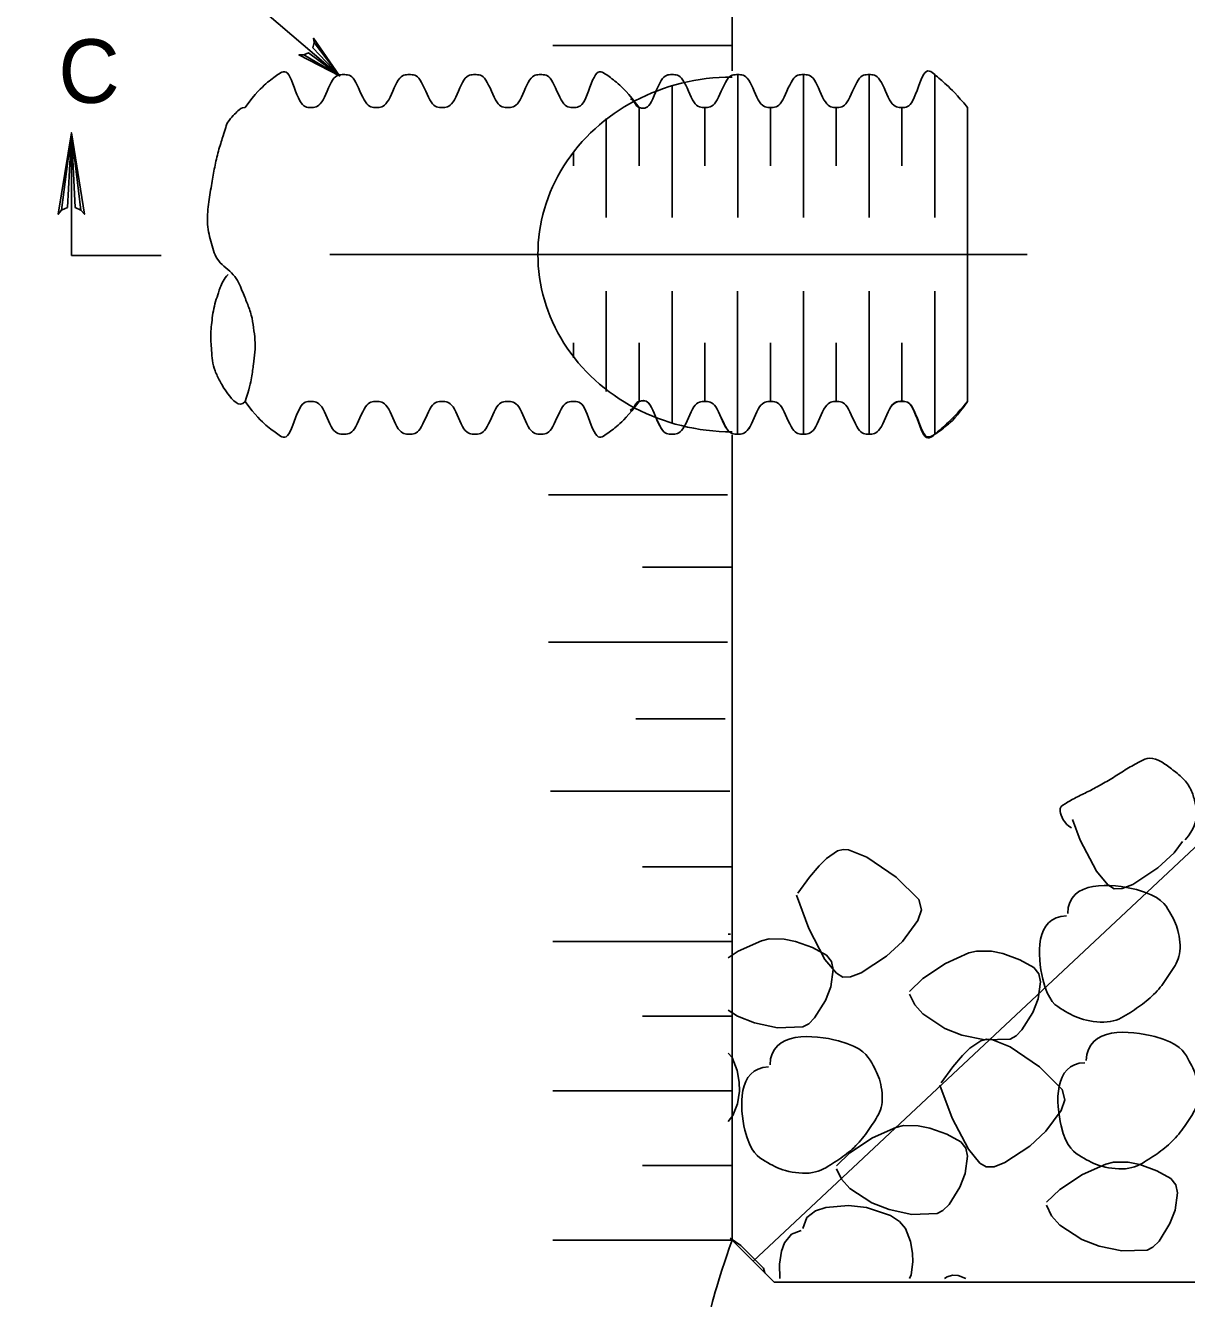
# Model space of a CAD drawing. Extents: x 636183 to 639890, y 299162 to 300538.
# Drawn here: x 638561.9 to 638653.3, y 300331.8 to 300431.9 of the extents above; entities that cross this region are included whole.
import ezdxf

# ---------------------------------------------------------------- set-up
doc = ezdxf.new("R2010")
doc.units = 0
doc.layers.add('Default', color=7, linetype='Continuous')

msp = doc.modelspace()

# ---------------------------------------------------------------- linework, layer by layer
at = {"layer": 'Default'}
for p, q in [((638617.52, 300491.43), (638617.52, 300428.36)), ((638617.52, 300430.36), (638603.43, 300430.36)), ((638617.97, 300416.82), (638617.97, 300428.06)), ((638623.13, 300416.82), (638623.13, 300428.06)), ((638628.3, 300416.82), (638628.3, 300428.06)), ((638633.47, 300416.82), (638633.47, 300428.06)), ((638612.8, 300416.82), (638612.8, 300427.15)), ((638610.22, 300420.89), (638610.22, 300425.48)), ((638615.38, 300420.89), (638615.38, 300425.48)), ((638620.55, 300420.89), (638620.55, 300425.48)), ((638625.72, 300420.89), (638625.72, 300425.48)), ((638630.89, 300420.89), (638630.89, 300425.48)), ((638636.05, 300425.48), (638636.05, 300402.36)), ((638607.63, 300416.82), (638607.63, 300424.61)), ((638565.55, 300413.83), (638565.55, 300423.49)), ((638605.05, 300420.88), (638605.05, 300421.97)), ((638572.6, 300413.83), (638565.55, 300413.83)), ((638640.74, 300413.92), (638585.88, 300413.92)), ((638607.63, 300403.15), (638607.63, 300411.02)), ((638612.8, 300400.62), (638612.8, 300411.02)), ((638617.96, 300399.78), (638617.96, 300411.02)), ((638623.13, 300399.78), (638623.13, 300411.02)), ((638628.3, 300399.78), (638628.3, 300411.02)), ((638633.47, 300399.78), (638633.47, 300411.02)), ((638605.05, 300405.79), (638605.05, 300406.96)), ((638610.21, 300402.36), (638610.21, 300406.96)), ((638615.38, 300402.36), (638615.38, 300406.96)), ((638620.55, 300402.36), (638620.55, 300406.96)), ((638625.72, 300402.36), (638625.72, 300406.96)), ((638630.89, 300402.37), (638630.89, 300406.96)), ((638617.52, 300399.74), (638617.52, 300336.41)), ((638617.17, 300395.02), (638603.07, 300395.02)), ((638617.52, 300389.32), (638610.47, 300389.32)), ((638617.17, 300383.44), (638603.07, 300383.44)), ((638616.99, 300377.39), (638609.94, 300377.39)), ((638617.34, 300371.7), (638603.25, 300371.7)), ((638619.18, 300334.75), (638656.07, 300369.29)), ((638644.9, 300367.87), (638644.3, 300369.49)), ((638624.94, 300366.42), (638625.82, 300367.01)), ((638625.82, 300367.01), (638626.26, 300367.13)), ((638626.26, 300367.13), (638626.68, 300367.11)), ((638626.68, 300367.11), (638628.13, 300366.53)), ((638646.18, 300365.43), (638644.9, 300367.87)), ((638652.96, 300367.75), (638652.29, 300366.85)), ((638624.37, 300365.85), (638624.94, 300366.42)), ((638628.13, 300366.53), (638630.43, 300364.96)), ((638652.29, 300366.85), (638651.02, 300365.68)), ((638617.52, 300365.77), (638610.47, 300365.77)), ((638623.62, 300364.95), (638624.37, 300365.85)), ((638647.08, 300364.34), (638646.18, 300365.43)), ((638651.02, 300365.68), (638649.04, 300364.38)), ((638622.7, 300363.69), (638623.62, 300364.95)), ((638630.43, 300364.96), (638632.21, 300363.18)), ((638647.58, 300364.04), (638647.08, 300364.34)), ((638648.2, 300364.06), (638647.58, 300364.04)), ((638649.04, 300364.38), (638648.2, 300364.06)), ((638623.55, 300360.92), (638622.59, 300363.52)), ((638632.21, 300363.18), (638632.42, 300362.38)), ((638632.42, 300362.38), (638632.14, 300361.53)), ((638632.14, 300361.53), (638630.94, 300359.9)), ((638617.41, 300360.47), (638617.22, 300360.47)), ((638619.83, 300359.94), (638620.43, 300360.1)), ((638620.43, 300360.1), (638621.61, 300360.08)), ((638621.61, 300360.08), (638622.52, 300359.89)), ((638624.83, 300358.48), (638623.55, 300360.92)), ((638617.52, 300359.9), (638603.43, 300359.9)), ((638617.22, 300358.6), (638618, 300359.12)), ((638618, 300359.12), (638619.83, 300359.94)), ((638622.52, 300359.89), (638623.84, 300359.41)), ((638623.84, 300359.41), (638624.96, 300358.81)), ((638630.94, 300359.9), (638629.67, 300358.73)), ((638634.31, 300358.16), (638636.14, 300358.99)), ((638636.14, 300358.99), (638636.75, 300359.14)), ((638636.75, 300359.14), (638637.92, 300359.13)), ((638637.92, 300359.13), (638638.83, 300358.94)), ((638625.73, 300357.39), (638624.83, 300358.48)), ((638624.96, 300358.81), (638625.35, 300358.31)), ((638625.35, 300358.31), (638625.47, 300357.68)), ((638629.67, 300358.73), (638627.69, 300357.43)), ((638632.54, 300356.99), (638634.31, 300358.16)), ((638638.83, 300358.94), (638640.16, 300358.45)), ((638640.16, 300358.45), (638641.27, 300357.85)), ((638625.47, 300357.68), (638625.28, 300356.32)), ((638626.23, 300357.09), (638625.73, 300357.39)), ((638626.85, 300357.11), (638626.23, 300357.09)), ((638627.69, 300357.43), (638626.85, 300357.11)), ((638631.48, 300355.97), (638632.54, 300356.99)), ((638641.27, 300357.85), (638641.66, 300357.35)), ((638641.66, 300357.35), (638641.78, 300356.72)), ((638625.28, 300356.32), (638624.87, 300355.26)), ((638641.78, 300356.72), (638641.59, 300355.37)), ((638624.87, 300355.26), (638624.02, 300353.88)), ((638631.89, 300354.91), (638631.48, 300355.74)), ((638641.59, 300355.37), (638641.19, 300354.3)), ((638617.52, 300354.03), (638610.47, 300354.03)), ((638617.95, 300354.01), (638617.22, 300354.48)), ((638619.3, 300353.49), (638617.95, 300354.01)), ((638632.52, 300354.19), (638631.89, 300354.91)), ((638634.26, 300353.05), (638632.52, 300354.19)), ((638641.19, 300354.3), (638640.33, 300352.93)), ((638621.1, 300353.11), (638619.3, 300353.49)), ((638623.08, 300353.17), (638621.1, 300353.11)), ((638623.55, 300353.41), (638623.08, 300353.17)), ((638624.02, 300353.88), (638623.55, 300353.41)), ((638635.61, 300352.53), (638634.26, 300353.05)), ((638637.41, 300352.15), (638635.61, 300352.53)), ((638636.22, 300351.49), (638637.1, 300352.08)), ((638637.1, 300352.08), (638637.53, 300352.2)), ((638639.39, 300352.21), (638637.41, 300352.15)), ((638637.53, 300352.2), (638637.96, 300352.18)), ((638637.96, 300352.18), (638639.4, 300351.6)), ((638639.86, 300352.46), (638639.39, 300352.21)), ((638640.33, 300352.93), (638639.86, 300352.46)), ((638617.22, 300351.12), (638617.52, 300350.77)), ((638635.64, 300350.92), (638636.22, 300351.49)), ((638639.4, 300351.6), (638641.7, 300350.02)), ((638617.52, 300350.77), (638617.92, 300349.74)), ((638633.98, 300348.77), (638634.9, 300350.02)), ((638634.9, 300350.02), (638635.64, 300350.92)), ((638641.7, 300350.02), (638643.48, 300348.25)), ((638617.92, 300349.74), (638618.08, 300348.83)), ((638617.52, 300348.15), (638603.43, 300348.15)), ((638618.11, 300348.13), (638617.96, 300347.11)), ((638618.08, 300348.83), (638618.11, 300348.13)), ((638634.83, 300345.99), (638633.86, 300348.6)), ((638643.48, 300348.25), (638643.69, 300347.45)), ((638617.96, 300347.11), (638617.58, 300346.21)), ((638643.69, 300347.45), (638643.42, 300346.6)), ((638617.58, 300346.21), (638617.22, 300345.73)), ((638636.11, 300343.55), (638634.83, 300345.99)), ((638643.42, 300346.6), (638642.21, 300344.97)), ((638628.57, 300344.44), (638630.4, 300345.26)), ((638630.4, 300345.26), (638631, 300345.41)), ((638631, 300345.41), (638632.17, 300345.4)), ((638632.17, 300345.4), (638633.09, 300345.21)), ((638633.09, 300345.21), (638634.41, 300344.73)), ((638642.21, 300344.97), (638640.95, 300343.8)), ((638626.79, 300343.26), (638628.57, 300344.44)), ((638634.41, 300344.73), (638635.52, 300344.13)), ((638635.52, 300344.13), (638635.92, 300343.63)), ((638625.73, 300342.25), (638626.79, 300343.26)), ((638636.04, 300343), (638635.85, 300341.64)), ((638635.92, 300343.63), (638636.04, 300343)), ((638637.01, 300342.46), (638636.11, 300343.55)), ((638640.95, 300343.8), (638638.97, 300342.5)), ((638617.52, 300342.28), (638610.47, 300342.28)), ((638626.14, 300341.19), (638625.73, 300342.02)), ((638637.51, 300342.16), (638637.01, 300342.46)), ((638638.13, 300342.18), (638637.51, 300342.16)), ((638638.97, 300342.5), (638638.13, 300342.18)), ((638645.09, 300341.57), (638646.92, 300342.39)), ((638646.92, 300342.39), (638647.52, 300342.54)), ((638647.52, 300342.54), (638648.69, 300342.53)), ((638648.69, 300342.53), (638649.61, 300342.34)), ((638649.61, 300342.34), (638650.93, 300341.86)), ((638626.78, 300340.46), (638626.14, 300341.19)), ((638635.85, 300341.64), (638635.44, 300340.57)), ((638643.31, 300340.39), (638645.09, 300341.57)), ((638650.93, 300341.86), (638652.04, 300341.26)), ((638652.04, 300341.26), (638652.44, 300340.75)), ((638628.51, 300339.33), (638626.78, 300340.46)), ((638635.44, 300340.57), (638634.59, 300339.2)), ((638642.25, 300339.38), (638643.31, 300340.39)), ((638652.56, 300340.13), (638652.37, 300338.77)), ((638652.44, 300340.75), (638652.56, 300340.13)), ((638624.08, 300338.7), (638624.91, 300338.98)), ((638624.91, 300338.98), (638626.68, 300339.12)), ((638626.68, 300339.12), (638628.09, 300338.96)), ((638628.09, 300338.96), (638629.99, 300338.34)), ((638629.87, 300338.81), (638628.51, 300339.33)), ((638634.59, 300339.2), (638634.11, 300338.73)), ((638642.66, 300338.32), (638642.25, 300339.15)), ((638623.09, 300337.33), (638623.4, 300338.18)), ((638623.4, 300338.18), (638624.08, 300338.7)), ((638631.67, 300338.43), (638629.87, 300338.81)), ((638629.99, 300338.34), (638630.7, 300337.88)), ((638633.65, 300338.49), (638631.67, 300338.43)), ((638634.11, 300338.73), (638633.65, 300338.49)), ((638643.3, 300337.59), (638642.66, 300338.32)), ((638652.37, 300338.77), (638651.96, 300337.7)), ((638622.19, 300336.88), (638622.97, 300337.15)), ((638630.7, 300337.88), (638631.17, 300337.33)), ((638631.17, 300337.33), (638631.57, 300336.3)), ((638645.04, 300336.46), (638643.3, 300337.59)), ((638651.96, 300337.7), (638651.11, 300336.33)), ((638617.52, 300336.41), (638603.43, 300336.41)), ((638617.37, 300336.56), (638618.22, 300335.98)), ((638617.52, 300336.41), (638620.84, 300333.09)), ((638618.22, 300335.98), (638620, 300334.2)), ((638621.42, 300335.53), (638621.66, 300336.18)), ((638621.66, 300336.18), (638622.19, 300336.88)), ((638631.57, 300336.3), (638631.73, 300335.39)), ((638646.39, 300335.94), (638645.04, 300336.46)), ((638651.11, 300336.33), (638650.63, 300335.86)), ((638621.26, 300334.52), (638621.42, 300335.53)), ((638631.73, 300335.39), (638631.75, 300334.69)), ((638648.19, 300335.56), (638646.39, 300335.94)), ((638650.17, 300335.62), (638648.19, 300335.56)), ((638650.63, 300335.86), (638650.17, 300335.62)), ((638620, 300334.2), (638620.09, 300333.83)), ((638621.28, 300333.38), (638621.26, 300334.52)), ((638631.75, 300334.69), (638631.61, 300333.67)), ((638620.84, 300333.09), (638750.03, 300333.09)), ((638631.61, 300333.67), (638631.49, 300333.38)), ((638634.23, 300333.38), (638634.44, 300333.52)), ((638634.44, 300333.52), (638634.87, 300333.64)), ((638634.87, 300333.64), (638635.31, 300333.62)), ((638635.31, 300333.62), (638635.9, 300333.38))]:
    msp.add_line(p, q, dxfattribs=at)
for points in [[(638586.65, 300427.96), (638566.63, 300445.07), (638544.4, 300445.07)], [(638584.65, 300430.58), (638584.6, 300430.92), (638586.65, 300427.96), (638584.65, 300430.58), (638584.55, 300430.17), (638586.65, 300427.96), (638584.21, 300429.77), (638583.83, 300429.61), (638586.65, 300427.96), (638583.45, 300429.61), (638583.83, 300429.61)], [(638564.78, 300417.39), (638565.23, 300417.62), (638565.55, 300423.49), (638564.78, 300417.39), (638564.52, 300417.08), (638565.55, 300423.49), (638565.84, 300417.62), (638566.28, 300417.41), (638565.55, 300423.49), (638566.57, 300417.08), (638566.28, 300417.41)]]:
    msp.add_lwpolyline(points, dxfattribs=at)
msp.add_ellipse((638617.52, 300413.92), major_axis=(-15.27, 0), ratio=0.913354, start_param=4.712389, end_param=7.853982, dxfattribs=at)
for points in [[(638610.21, 300425.48), (638609.35, 300426.62), (638608.49, 300427.45), (638607.63, 300428.06), (638606.77, 300428.67), (638605.91, 300425.48), (638605.05, 300425.48), (638604.18, 300425.48), (638603.32, 300428.06), (638602.46, 300428.06), (638601.6, 300428.06), (638600.74, 300425.48), (638599.88, 300425.48), (638599.02, 300425.48), (638598.16, 300428.06), (638597.29, 300428.06), (638596.43, 300428.06), (638595.57, 300425.48), (638594.71, 300425.48), (638593.85, 300425.48), (638592.99, 300428.06), (638592.13, 300428.06), (638591.27, 300428.06), (638590.4, 300425.48), (638589.54, 300425.48), (638588.68, 300425.48), (638587.82, 300428.06), (638586.96, 300428.06), (638586.1, 300428.06), (638585.24, 300425.48), (638584.38, 300425.48), (638583.51, 300425.48), (638582.65, 300428.67), (638581.79, 300428.06), (638580.93, 300427.45), (638580.07, 300426.62), (638579.21, 300425.48)], [(638609.54, 300426.15), (638609.76, 300426.1), (638609.99, 300425.53), (638610.21, 300425.48), (638611.08, 300425.26), (638611.94, 300428.06), (638612.8, 300428.06), (638613.66, 300428.06), (638614.52, 300425.48), (638615.38, 300425.48), (638616.24, 300425.48), (638617.11, 300428.06), (638617.97, 300428.06), (638618.83, 300428.06), (638619.69, 300425.48), (638620.55, 300425.48), (638621.41, 300425.48), (638622.27, 300428.06), (638623.13, 300428.06), (638624, 300428.06), (638624.86, 300425.48), (638625.72, 300425.48), (638626.58, 300425.48), (638627.44, 300428.06), (638628.3, 300428.06), (638629.16, 300428.06), (638630.02, 300425.48), (638630.89, 300425.48), (638631.75, 300425.48), (638632.61, 300428.78), (638633.47, 300428.06), (638634.33, 300427.34), (638635.19, 300426.49), (638636.05, 300425.48)], [(638579.21, 300425.48), (638578.92, 300425.47), (638578.62, 300425.19), (638578.33, 300424.89), (638577.79, 300424.32), (638577.66, 300423.76), (638577.45, 300423.13), (638577.05, 300421.89), (638576.78, 300420.64), (638576.57, 300419.38), (638576.32, 300417.87), (638576.17, 300416.26), (638576.57, 300414.76), (638576.96, 300413.32), (638578.43, 300412.4), (638579, 300411.02), (638579.38, 300410.09), (638579.74, 300409.15), (638579.88, 300408.16), (638580.01, 300407.21), (638580, 300406.24), (638579.88, 300405.29), (638579.74, 300404.3), (638579.55, 300403.33), (638579.21, 300402.36)], [(638579.21, 300402.36), (638578.77, 300401.81), (638577.65, 300403.16), (638577.23, 300403.97), (638576.82, 300404.77), (638576.63, 300405.56), (638576.57, 300406.4), (638576.52, 300407.05), (638576.51, 300407.72), (638576.57, 300408.38), (638576.65, 300409.12), (638576.78, 300409.85), (638577.01, 300410.58), (638577.21, 300411.22), (638577.53, 300412.03), (638577.89, 300412.34)], [(638610.21, 300402.36), (638609.35, 300401.22), (638608.49, 300400.39), (638607.63, 300399.78), (638606.77, 300399.17), (638605.91, 300402.36), (638605.05, 300402.36), (638604.18, 300402.36), (638603.32, 300399.78), (638602.46, 300399.78), (638601.6, 300399.78), (638600.74, 300402.36), (638599.88, 300402.36), (638599.02, 300402.36), (638598.16, 300399.78), (638597.29, 300399.78), (638596.43, 300399.78), (638595.57, 300402.36), (638594.71, 300402.36), (638593.85, 300402.36), (638592.99, 300399.78), (638592.13, 300399.78), (638591.27, 300399.78), (638590.4, 300402.36), (638589.54, 300402.36), (638588.68, 300402.36), (638587.82, 300399.78), (638586.96, 300399.78), (638586.1, 300399.78), (638585.24, 300402.36), (638584.38, 300402.36), (638583.51, 300402.36), (638582.65, 300399.17), (638581.79, 300399.78), (638580.93, 300400.39), (638580.07, 300401.22), (638579.21, 300402.36)], [(638636.05, 300402.36), (638635.19, 300401.16), (638634.33, 300400.35), (638633.47, 300399.78), (638632.61, 300399.21), (638631.75, 300402.37), (638630.89, 300402.37), (638630.02, 300402.37), (638629.16, 300399.78), (638628.3, 300399.78), (638627.44, 300399.78), (638626.58, 300402.36), (638625.72, 300402.36), (638624.86, 300402.36), (638624, 300399.78), (638623.13, 300399.78), (638622.27, 300399.78), (638621.41, 300402.36), (638620.55, 300402.36), (638619.69, 300402.36), (638618.83, 300399.78), (638617.96, 300399.78), (638617.1, 300399.78), (638616.24, 300402.36), (638615.38, 300402.36), (638614.52, 300402.36), (638613.66, 300399.78), (638612.8, 300399.78), (638611.94, 300399.78), (638611.07, 300402.57), (638610.21, 300402.36), (638609.98, 300402.31), (638609.74, 300401.71), (638609.5, 300401.65)], [(638609.54, 300401.69), (638609.76, 300401.75), (638609.99, 300402.31), (638610.21, 300402.36), (638611.08, 300402.58), (638611.94, 300399.78), (638612.8, 300399.78), (638613.66, 300399.78), (638614.52, 300402.36), (638615.38, 300402.36), (638616.24, 300402.36), (638617.11, 300399.78), (638617.97, 300399.78), (638618.83, 300399.78), (638619.69, 300402.36), (638620.55, 300402.36), (638621.41, 300402.36), (638622.27, 300399.78), (638623.13, 300399.78), (638624, 300399.78), (638624.86, 300402.36), (638625.72, 300402.36), (638626.58, 300402.36), (638627.44, 300399.78), (638628.3, 300399.78), (638629.16, 300399.78), (638630.02, 300402.36), (638630.89, 300402.36), (638631.75, 300402.36), (638632.61, 300399.06), (638633.47, 300399.78), (638634.33, 300400.5), (638635.19, 300401.35), (638636.05, 300402.36)], [(638653.18, 300367.89), (638653.9, 300368.74), (638654.16, 300369.94), (638653.93, 300370.88), (638653.68, 300371.85), (638653.05, 300372.73), (638652.06, 300373.49), (638651.29, 300374.08), (638650.35, 300374.43), (638649.64, 300374.05), (638648.57, 300373.48), (638647.52, 300372.78), (638646.46, 300372.18), (638645.55, 300371.67), (638644.56, 300371.22), (638643.66, 300370.69), (638643.11, 300370.37), (638643.64, 300369.16), (638644.22, 300368.82)], [(638643.93, 300362.08), (638643.97, 300364.77), (638650.86, 300364.16), (638652.02, 300362.08), (638652.67, 300360.9), (638652.9, 300358.78), (638652.07, 300357.52), (638651.26, 300356.27), (638650.13, 300355.15), (638648.89, 300354.33), (638647.44, 300353.39), (638644.98, 300353.68), (638643.65, 300354.45), (638641.75, 300355.54), (638641.33, 300361.85), (638643.82, 300361.91)], [(638645.39, 300350.53), (638645.42, 300353.22), (638652.31, 300352.61), (638653.47, 300350.53), (638654.12, 300349.36), (638654.35, 300347.24), (638653.53, 300345.97), (638652.71, 300344.73), (638651.58, 300343.6), (638650.34, 300342.79), (638648.89, 300341.85), (638646.44, 300342.13), (638645.1, 300342.9), (638643.2, 300343.99), (638642.79, 300350.3), (638645.27, 300350.36)], [(638620.51, 300350.19), (638620.54, 300352.88), (638627.43, 300352.27), (638628.59, 300350.19), (638629.24, 300349.02), (638629.47, 300346.9), (638628.65, 300345.64), (638627.83, 300344.39), (638626.7, 300343.26), (638625.46, 300342.45), (638624.01, 300341.51), (638621.55, 300341.79), (638620.22, 300342.56), (638618.32, 300343.65), (638617.91, 300349.96), (638620.39, 300350.02)], [(638617.52, 300336.41), (638616.33, 300332.95), (638615.36, 300329.48), (638615.16, 300325.89), (638615.07, 300324.34), (638615.21, 300322.79), (638615.16, 300321.25)]]:
    msp.add_open_spline(points, degree=3, dxfattribs=at)

# ---------------------------------------------------------------- texts
msp.add_text('C', height=5, dxfattribs=at).set_placement((638564.52, 300425.84))

doc.saveas('drawing.dxf')
